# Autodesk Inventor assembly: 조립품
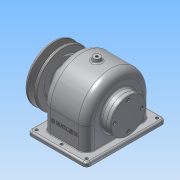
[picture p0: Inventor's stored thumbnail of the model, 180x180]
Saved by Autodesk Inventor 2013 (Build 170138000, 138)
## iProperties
Created: 2015-09
Part Number: 조립품
Document SubType Name: Assembly
Designer: Administrator
Author: Administrator
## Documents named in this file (14)
- D:\450908v1001\조립품.iam
- D:\450908v1001\본체.ipt
- D:\450908v1001\450908v1001\축.ipt
- D:\450908v1001\450908v1001\V-벨트풀리.ipt
- D:\450908v1001\450908v1001\멈춤나사 - M4x10.ipt
- D:\450908v1001\450908v1001\키 - 5 x 5 x 18.ipt
- D:\450908v1001\450908v1001\오일 실 17 32 8.ipt
- D:\450908v1001\450908v1001\앞커버.ipt
- D:\450908v1001\450908v1001\뒤커버.ipt
- D:\450908v1001\450908v1001\볼트 M3 x 10.ipt
- D:\450908v1001\450908v1001\베어링 6203.ipt
- D:\450908v1001\450908v1001\키 - 6 x 6 x 22.ipt
- D:\450908v1001\450908v1001\스퍼기어.ipt
- D:\450908v1001\450908v1001\볼트 M3 x 8.ipt
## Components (9 placed, 3 different names)
1. V-벨트풀리:1
2. ISO 4762 M3 x 10:1
3. ISO 4762 M3 x 10:2
4. ISO 4762 M3 x 10:3
5. ISO 4762 M3 x 10:4
6. ISO 4762 M3 x 8:1
7. ISO 4762 M3 x 8:2
8. ISO 4762 M3 x 8:3
9. ISO 4762 M3 x 8:4
